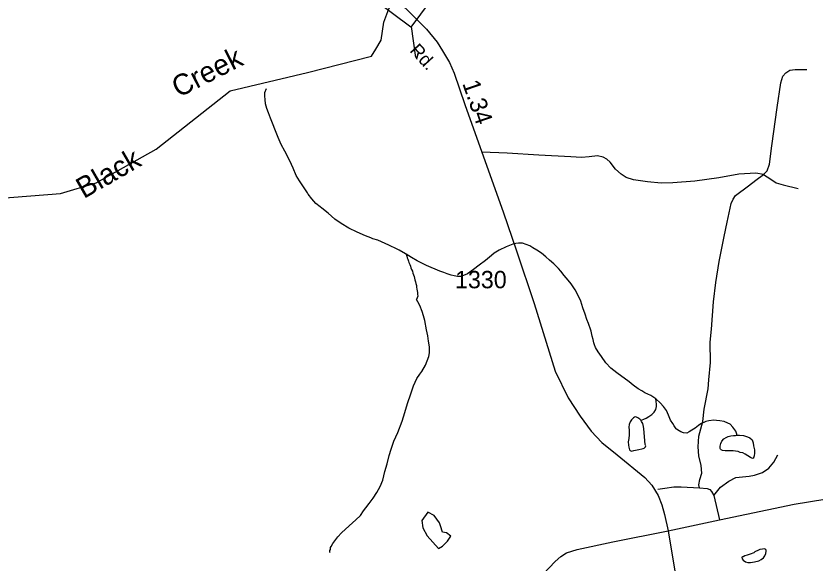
# Model space of a CAD drawing. Extents: x 2082433 to 2279600, y 546599 to 755198.
# Drawn here: x 2142696 to 2148448, y 623711 to 627650 of the extents above; entities that cross this region are included whole.
import ezdxf

# ---------------------------------------------------------------- set-up
doc = ezdxf.new("R2010")
doc.units = 0
for name, color, linetype in [('Exist Hydrographic Creek Single Shore', 7, 'Continuous'), ('Exist Hydrographic Creek Single Shore Label', 7, 'Continuous'), ('Exist Hydrographic Misc Water Feature', 7, 'Continuous'), ('Exist Hydrographic Pond Over 1500 Sq Ft', 7, 'Continuous'), ('Exist Road Non-System Type 51', 7, 'Continuous'), ('Exist Road Secondary Mileage Hundredths English Label', 7, 'Continuous'), ('Exist Road Secondary Structure Standard Bridge CELL', 7, 'Continuous'), ('Exist Road Secondary Type 51 Attributed', 7, 'Continuous'), ('Exist Road Secondary Type 51 Label', 7, 'Continuous'), ('Exist Road Secondary Type 51 Number Label', 7, 'Continuous')]:
    doc.layers.add(name, color=color, linetype=linetype)

msp = doc.modelspace()

# ---------------------------------------------------------------- linework, layer by layer
at = {"layer": 'Exist Hydrographic Creek Single Shore'}
msp.add_lwpolyline([(2142341.3, 626319), (2143015.3, 626371), (2143273.3, 626447.7), (2143705.3, 626691.6), (2144237.2, 627110.5), (2144794.4, 627243.6), (2145254.9, 627360.2), (2145287.1, 627411.7), (2145325.7, 627476.1), (2145345, 627604.9), (2145380.2, 627700.4), (2145430.4, 627775.8), (2145520, 627889.1), (2145543, 627932.9), (2145563.9, 628023.4), (2145456.3, 628289.7), (2145339.4, 628423.4), (2145322.4, 628554.9), (2145371.4, 628672), (2145604.3, 628749.3)], dxfattribs=at)
at = {"layer": 'Exist Hydrographic Misc Water Feature'}
for points in [[(2144897.9, 626266.9), (2144886, 626276.8), (2144853.8, 626300.8), (2144825.5, 626332.6), (2144799.5, 626368.2), (2144793.7, 626376.4), (2144737.3, 626464), (2144713.1, 626502.1), (2144690.6, 626553.8), (2144666.4, 626607.7), (2144632.4, 626675.8), (2144604.1, 626723.4), (2144584, 626775.5), (2144563.5, 626823.3), (2144543.6, 626877.4), (2144529.4, 626915.2), (2144514.9, 626953.1), (2144502.8, 626982.9), (2144492.7, 627016.8), (2144488.8, 627048.7), (2144486.4, 627073), (2144488.2, 627098.6), (2144498.3, 627128.8)], [(2145250.6, 626052.6), (2145212.7, 626066.5), (2145152.6, 626094.2), (2145092.7, 626121.9), (2145036.1, 626155.6), (2144992.2, 626187.4), (2144944.2, 626231.1), (2144897.9, 626266.9)], [(2145300.8, 626036.9), (2145264.9, 626046.4), (2145250.6, 626052.6)], [(2145439, 625971.4), (2145380.8, 625999.3), (2145300.8, 626036.9)], [(2147303.2, 624893.8), (2147267.1, 624917.4), (2147222.8, 624937.5), (2147200.8, 624951.4), (2147174.8, 624965.1), (2147139.1, 624991.2), (2147110.8, 625014.9), (2147020.6, 625080.5), (2146978.6, 625114.4), (2146942.1, 625152.4), (2146910.1, 625197.8), (2146887.7, 625231.9), (2146867.4, 625263.8), (2146859.8, 625281.6), (2146855.7, 625297.6), (2146851.2, 625319.8), (2146843.4, 625343.7), (2146836.9, 625381.6), (2146835, 625387.5), (2146817, 625435.3), (2146805.1, 625465.5), (2146792.6, 625503.4), (2146776.4, 625549.3), (2146761.8, 625597.3), (2146737.8, 625647.2), (2146722, 625679.2), (2146693.7, 625720.8), (2146671.6, 625748.9), (2146643.3, 625780.7), (2146619.3, 625812.8), (2146601.3, 625832.5), (2146567, 625866.1), (2146536.9, 625892.1), (2146510.6, 625915.9), (2146478.9, 625941.9), (2146444.6, 625963.7), (2146416.7, 625981.7), (2146394.8, 625995.6), (2146368.7, 626005.1), (2146342.5, 626013.2), (2146314.8, 626013.3), (2146294.5, 626011.1), (2146272.6, 626007.1), (2146224.4, 625988.8), (2146175, 625964.7), (2146138.9, 625942.6), (2146119, 625924.5), (2146077.2, 625890.3), (2146031.4, 625855.8), (2145989.4, 625823.6), (2145945.5, 625793.8), (2145917.4, 625781.4), (2145896.1, 625775.3), (2145873.9, 625775.4), (2145851.6, 625779.2), (2145828, 625783.2), (2145799.5, 625793.2), (2145775.7, 625802.9), (2145747.4, 625812.8), (2145651.7, 625854.4), (2145583.2, 625887.9), (2145543.4, 625911.8), (2145504.9, 625935.8)], [(2145504.9, 625935.8), (2145499.3, 625937.5), (2145455, 625963.3), (2145439, 625971.4)], [(2145504.9, 625935.8), (2145509.4, 625921.8), (2145513.3, 625909.8), (2145517.4, 625897.9), (2145521.3, 625885.5), (2145525.2, 625874), (2145531.3, 625859.7), (2145535.6, 625847.7), (2145539.7, 625835.7), (2145543.6, 625823.7), (2145549.8, 625811.9), (2145553.9, 625797.9), (2145557.8, 625785.9), (2145561.7, 625773.9), (2145565.5, 625762), (2145567.8, 625749.9), (2145571.9, 625735.9), (2145573.8, 625723.9), (2145578.3, 625709.8), (2145580.1, 625698.2), (2145582.4, 625684), (2145584.2, 625672), (2145586.1, 625657.9), (2145586.3, 625646.2), (2145588.1, 625632.1), (2145580.3, 625608.1)], [(2144956.8, 623785.8), (2144956.5, 623789.8), (2144956.3, 623802), (2144960.2, 623810), (2144960.6, 623822.1), (2144964.5, 623830), (2144976.2, 623852.2), (2144990.2, 623871.9), (2145014, 623900.4), (2145040, 623928.1), (2145093.7, 623978.4), (2145141.5, 624022.7), (2145175.3, 624054.8), (2145197.3, 624086.8), (2145214.9, 624108.9), (2145239.1, 624140.9), (2145266.6, 624179.3), (2145294.7, 624219.3), (2145318.7, 624261.5), (2145336.5, 624307.5), (2145351.9, 624369.6), (2145368.1, 624425.6), (2145383.7, 624485.7), (2145397.2, 624531.5), (2145417.1, 624587.7), (2145445, 624650), (2145476.6, 624732), (2145496, 624796), (2145515.7, 624859.9), (2145537.5, 624930), (2145557.3, 624988.2), (2145580.9, 625040.2), (2145602.9, 625070.2), (2145618.7, 625090.5), (2145644.7, 625136.4), (2145668.1, 625198.6), (2145672.2, 625224.8), (2145672.2, 625268.5), (2145665.6, 625308.5), (2145659.7, 625346.3), (2145651.7, 625390.5), (2145639, 625456.5), (2145630.8, 625492.2), (2145620.5, 625522.1), (2145604.5, 625564.3), (2145588.3, 625592.3), (2145580.3, 625608.1)], [(2147194.1, 624739.5), (2147203.7, 624741.3), (2147215.8, 624747.6), (2147233.6, 624755.4), (2147251.5, 624765.7), (2147273.8, 624781.8), (2147289.6, 624797.6), (2147303.4, 624815.8), (2147307.5, 624837.9), (2147307.1, 624853.8), (2147305.2, 624876), (2147303.2, 624893.8)], [(2147886.1, 624632.4), (2147886.3, 624638.5), (2147881.8, 624652.5), (2147877.9, 624660.4), (2147871.6, 624670.3), (2147857.8, 624690.2), (2147837.5, 624710.3), (2147821.7, 624718), (2147793.4, 624730), (2147763.5, 624735.7), (2147737.9, 624737.6), (2147719.4, 624739.6), (2147683.5, 624735.7), (2147661.6, 624729.2), (2147625.7, 624713.2), (2147609.7, 624701.4), (2147585.5, 624683.1), (2147560.3, 624669.1), (2147542, 624654.8), (2147525.8, 624646.7), (2147502.1, 624648.7), (2147482, 624656.6), (2147469.9, 624662.5), (2147451.8, 624674.6), (2147448.3, 624678.4), (2147433.8, 624698.4), (2147423.5, 624716.5), (2147407.5, 624740.5), (2147393.6, 624776.3), (2147379.2, 624810.1), (2147357.1, 624838.1), (2147333.1, 624864.1), (2147303.2, 624893.8)], [(2147194.1, 624739.5), (2147186.1, 624747.2), (2147173.6, 624757.2), (2147163.7, 624761.1), (2147157.6, 624763.2), (2147149.6, 624761.2), (2147141.8, 624757.1), (2147127.8, 624743), (2147117.6, 624727.2), (2147110, 624709.2), (2147108.4, 624688.8), (2147110.2, 624667), (2147110.4, 624634.9), (2147108.2, 624608.9), (2147104.3, 624583.2), (2147106.5, 624560.9), (2147108.6, 624545.2), (2147112.9, 624527.1), (2147118.6, 624521.4), (2147126.8, 624517.3), (2147144.9, 624521), (2147167, 624525.4), (2147180.7, 624529.4), (2147202.7, 624533.4), (2147210.7, 624535.4), (2147218.5, 624539.5), (2147228.5, 624547.7), (2147230.6, 624555.5), (2147226.3, 624565.5), (2147216, 624677.4), (2147213.6, 624693.6), (2147208, 624715.5), (2147200, 624731.3), (2147194.1, 624739.5)], [(2147886.1, 624632.4), (2147904.4, 624632.5), (2147934.3, 624628.4), (2147962, 624620.9), (2147980.2, 624612.9), (2147996, 624598.7), (2148002.2, 624577.2), (2148006.3, 624555.1), (2148012.2, 624527), (2148012.4, 624503), (2148010.8, 624483), (2148006.3, 624469), (2148004.8, 624465.2), (2147998.5, 624464.9), (2147984.5, 624470.7), (2147964.9, 624482.6), (2147946.4, 624494.7), (2147928.6, 624504.7), (2147910.5, 624506.6), (2147894.5, 624514.4), (2147874.8, 624516.5), (2147858.6, 624518.6), (2147836.5, 624518.3), (2147818.7, 624518.1), (2147800.6, 624518), (2147782.6, 624522), (2147772.7, 624525.9), (2147768.6, 624530.1), (2147764.5, 624536), (2147764.3, 624551.9), (2147770.3, 624572.1), (2147778.3, 624589.9), (2147792, 624606.1), (2147808.2, 624616.2), (2147824, 624622.3), (2147842, 624628.1), (2147860.3, 624630.3), (2147875.9, 624630.3), (2147886.1, 624632.4)], [(2148015.3, 623793.2), (2148007.7, 623785.5), (2147981.3, 623775.3), (2147959.9, 623769.2), (2147941.9, 623763), (2147931.9, 623756.8), (2147926.1, 623754.9), (2147921.8, 623753), (2147923.6, 623741), (2147931.9, 623730.9), (2147948, 623721.1), (2147964, 623715), (2147983.7, 623715.3), (2148011.8, 623721.2), (2148043.8, 623727.3), (2148061.6, 623737.6), (2148077.6, 623749.3), (2148087.3, 623763.7), (2148093.8, 623779.8), (2148095.5, 623797.8), (2148097.5, 623801.5), (2148093.8, 623807.8), (2148083.8, 623813.7), (2148069.9, 623811.4), (2148051.6, 623809.2), (2148037.5, 623801.2), (2148019.6, 623793.4), (2148015.3, 623793.2)]]:
    msp.add_lwpolyline(points, dxfattribs=at)
at = {"layer": 'Exist Hydrographic Pond Over 1500 Sq Ft'}
msp.add_lwpolyline([(2145661.5, 624077.4), (2145618.4, 624018.1), (2145623.8, 623964.3), (2145656.1, 623907.7), (2145737, 623816.1), (2145766.6, 623832.2), (2145801.6, 623870), (2145825.9, 623905), (2145796.2, 623929.2), (2145766.6, 623934.6), (2145753.1, 623980.4), (2145745, 624002), (2145707.3, 624053.2)], close=True, dxfattribs=at)
at = {"layer": 'Exist Road Non-System Type 51'}
msp.add_line((2147720.7, 624198.5), (2147760.9, 624021.8), dxfattribs=at)
for points in [[(2148077.6, 626508.7), (2148104.9, 626536), (2148120.7, 626582), (2148136.5, 626715.6), (2148174.6, 626990.6), (2148201.2, 627169.4), (2148217, 627216.8), (2148238.5, 627241.2), (2148267.2, 627259.9), (2148304.6, 627265.7), (2148389.3, 627265.7)], [(2148077.6, 626508.7), (2148021.6, 626517.4), (2147899.5, 626511.6), (2147755.9, 626484.3), (2147582.1, 626461.3), (2147424.8, 626447.7), (2147340.1, 626446.3), (2147242.4, 626454.9), (2147140.5, 626470.7), (2147088.7, 626486.5), (2147052.8, 626510.9), (2147012.6, 626546.8), (2146973.8, 626597.1), (2146950.1, 626619.3), (2146924.3, 626633.7), (2146882.6, 626643.7), (2146822.3, 626636.6), (2146767.7, 626630.8), (2146690.2, 626635.1), (2146460.4, 626648.1), (2146232.7, 626663.1), (2146048.9, 626670.3)], [(2147617.3, 624253), (2147610.8, 624273.9), (2147618, 624312.6), (2147633.8, 624357.2), (2147629.5, 624414.6), (2147612.3, 624482.1), (2147606.5, 624546.8), (2147612.3, 624625.8), (2147640.3, 624731.3), (2147650.3, 624818.9), (2147679.1, 624965.4), (2147684.1, 625030.8), (2147695.6, 625154.3), (2147692.7, 625302.3), (2147703.5, 625394.9), (2147718.6, 625592.4), (2147734.4, 625731.7), (2147757.3, 625881.1), (2147794, 626062.8), (2147815.5, 626166.2), (2147845, 626299), (2147859.3, 626332.1), (2147876.6, 626356.5), (2147968.5, 626426.9), (2148021.6, 626468.5), (2148077.6, 626508.7)], [(2148077.6, 626508.7), (2148129.3, 626474.3), (2148169.6, 626449.8), (2148219.8, 626434), (2148326.1, 626408.2)], [(2147720.7, 624198.5), (2147768.1, 624257.3), (2147827, 624301.9), (2147878.7, 624326.3), (2147973.5, 624336.3), (2148013.7, 624343.5), (2148070.5, 624362.9), (2148116.4, 624394.5), (2148152.3, 624437.6), (2148181, 624490.7)], [(2147316.4, 624242.3), (2147367.4, 624250.2), (2147432, 624260.2), (2147483.7, 624258.8), (2147617.3, 624253)], [(2147617.3, 624253), (2147671.9, 624248.7), (2147690.6, 624240.1), (2147702, 624227.2), (2147720.7, 624198.5)]]:
    msp.add_lwpolyline(points, dxfattribs=at)
at = {"layer": 'Exist Road Secondary Structure Standard Bridge CELL'}
msp.add_line((2145541.2, 627573.8), (2145573.2, 627349.8), dxfattribs=at)
msp.add_lwpolyline([(2145281, 628053.2), (2145677.6, 627755.8), (2145538.7, 627570.5), (2145142, 627867.9)], close=True, dxfattribs=at)
at = {"layer": 'Exist Road Secondary Type 51 Attributed'}
for points in [[(2145430.4, 627775.8), (2145570.1, 627637.5), (2145652.2, 627554.7), (2145727.9, 627462.3), (2145766.7, 627399.4), (2145816.6, 627314.4), (2145851.6, 627237.6), (2145926.3, 627012.2), (2146048.9, 626670.3), (2146202.1, 626239.4), (2146298.3, 625957.9), (2146426.2, 625578.7), (2146577.5, 625091.8), (2146672.3, 624900.7), (2146757.7, 624768), (2146836.7, 624660.2), (2146912.8, 624578.4), (2147024.8, 624489.3), (2147222.2, 624328), (2147273.4, 624271.4), (2147317.9, 624198.7), (2147344.8, 624131.3), (2147363.7, 624061.3), (2147392, 623942.7)], [(2147392, 623942.7), (2147760.9, 624021.8), (2148298.5, 624135.6), (2148519.4, 624172.2), (2149092.7, 624231.9), (2149499.8, 624242.4), (2149955.1, 624247.4), (2150337, 624246.6), (2151102, 624266.9)], [(2145461.8, 622773.4), (2145688.5, 622883.8), (2145790.8, 622944.5), (2145909.4, 623036.1), (2146018.5, 623133.1), (2146578.3, 623721.8), (2146618.7, 623758.1), (2146659.1, 623783.7), (2146736.4, 623809.4), (2146993.8, 623863.8), (2147392, 623942.7)], [(2147392, 623942.7), (2147486.9, 623363.4), (2147569.1, 622902.7), (2147644.6, 622425.8), (2147710.6, 622024.3), (2147821, 621396.6), (2147912.6, 620873.9), (2147971.9, 620565.4), (2147993.5, 620487.2), (2148053.4, 620291.9), (2148176.7, 619964.5), (2148240, 619750.3), (2148338.3, 619367), (2148412.4, 619015.4)]]:
    msp.add_lwpolyline(points, dxfattribs=at)

# ---------------------------------------------------------------- texts
at = {"layer": 'Exist Hydrographic Creek Single Shore Label'}
for s, rotation, p in [('Creek', 26.88041, (2143865.8, 627059.1)), ('Black', 29.99179, (2143184.3, 626331.3))]:
    msp.add_text(s, height=150, rotation=rotation, dxfattribs=at).set_placement(p)
at = {"layer": 'Exist Road Secondary Mileage Hundredths English Label'}
msp.add_text('1.34', height=125, rotation=288.94966, dxfattribs=at).set_placement((2145908, 627164.8))
at = {"layer": 'Exist Road Secondary Type 51 Label'}
msp.add_text('Rd.', height=95, rotation=312.62709, dxfattribs=at).set_placement((2145525.3, 627396.7))
at = {"layer": 'Exist Road Secondary Type 51 Number Label'}
msp.add_text('1330', height=125, dxfattribs=at).set_placement((2145856.8, 625689.5))

doc.saveas('drawing.dxf')
